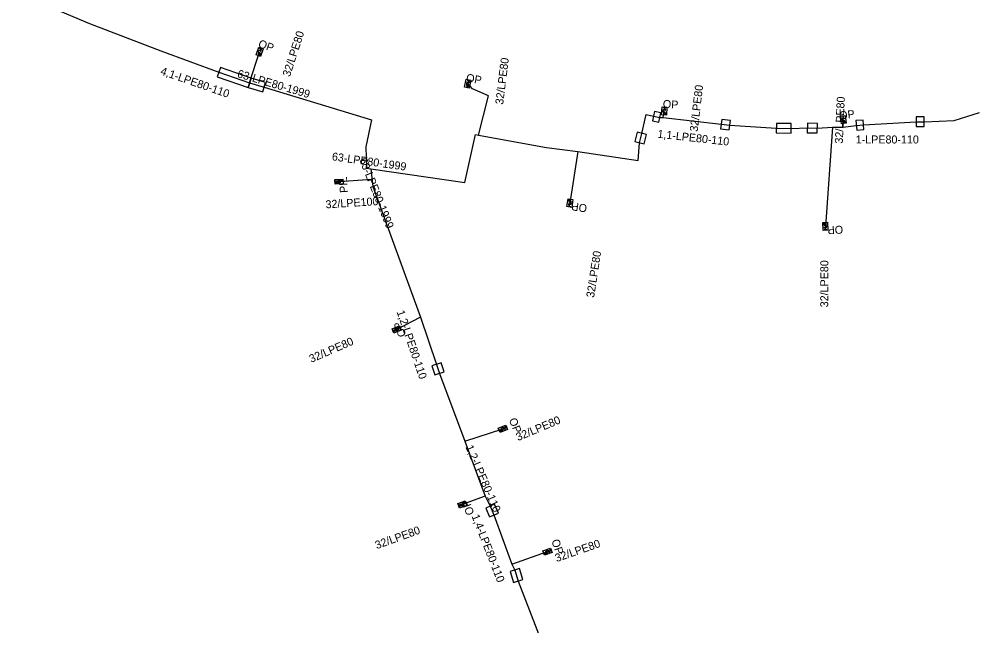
# Model space of a CAD drawing. Extents: x -762509 to -761250, y -1153000 to -1152256.
# Drawn here: x -761556.9 to -761437.4, y -1152409.7 to -1152334 of the extents above; entities that cross this region are included whole.
import ezdxf

# ---------------------------------------------------------------- set-up
doc = ezdxf.new("R2010")
doc.units = 0
for name, color, linetype in [('Vrstva 21', 7, 'Continuous'), ('Vrstva 29', 7, 'Continuous'), ('Vrstva 31', 7, 'Continuous'), ('Vrstva 32', 7, 'Continuous')]:
    doc.layers.add(name, color=color, linetype=linetype)

msp = doc.modelspace()

# ---------------------------------------------------------------- linework, layer by layer
at = {"layer": 'Vrstva 21'}
for points in [[(-761582.89, -1152319.81), (-761579.97, -1152321.01), (-761566.93, -1152326.59), (-761564.15, -1152327.67), (-761562.41, -1152328.48), (-761561.34, -1152328.94), (-761548.12, -1152334.52), (-761539.24, -1152337.93), (-761531.97, -1152340.58), (-761528.13, -1152341.92), (-761526.3, -1152342.45), (-761512.91, -1152346.54), (-761513.62, -1152349.91), (-761513.51, -1152352.59), (-761512.99, -1152352.67)], [(-761512.99, -1152352.67), (-761501.24, -1152354.37), (-761499.92, -1152348.35), (-761499.54, -1152348.44), (-761491.06, -1152349.98), (-761487.11, -1152350.48), (-761479.58, -1152351.6), (-761479.41, -1152349.39), (-761479.14, -1152348.23), (-761478.58, -1152345.89), (-761477.67, -1152346.08), (-761476.89, -1152346.26), (-761476.46, -1152346.24), (-761469.21, -1152347.08), (-761468.14, -1152347.2), (-761462.33, -1152347.58), (-761460.48, -1152347.61), (-761458.44, -1152347.54), (-761457.21, -1152347.58), (-761455.3, -1152347.46), (-761454.02, -1152347.46), (-761452.33, -1152347.23), (-761451.42, -1152347.16), (-761444.84, -1152346.77), (-761443.87, -1152346.77), (-761440.11, -1152346.61), (-761436.95, -1152345.64)], [(-761512.99, -1152352.67), (-761512.75, -1152354.87), (-761506.77, -1152371.17), (-761504.79, -1152377.08), (-761504.41, -1152378.2), (-761501.26, -1152386.66), (-761500.37, -1152389.03), (-761498.7, -1152393.56), (-761498.08, -1152394.78), (-761497.6, -1152395.89), (-761495.38, -1152402.02), (-761495, -1152402.77), (-761494.58, -1152404.14), (-761490.85, -1152413.85)]]:
    msp.add_lwpolyline(points, dxfattribs=at)
at = {"layer": 'Vrstva 29'}
for points in [[(-761532.17, -1152341.15), (-761528.33, -1152342.49), (-761527.93, -1152341.35), (-761531.77, -1152340.01)], [(-761528.3, -1152342.5), (-761526.47, -1152343.03), (-761526.13, -1152341.87), (-761527.96, -1152341.34)], [(-761477.8, -1152346.66), (-761477.02, -1152346.84), (-761476.76, -1152345.68), (-761477.54, -1152345.5)], [(-761469.28, -1152347.68), (-761468.21, -1152347.8), (-761468.07, -1152346.6), (-761469.14, -1152346.48)], [(-761452.28, -1152347.83), (-761451.37, -1152347.76), (-761451.47, -1152346.56), (-761452.38, -1152346.63)], [(-761444.84, -1152347.37), (-761443.87, -1152347.37), (-761443.87, -1152346.17), (-761444.84, -1152346.17)], [(-761462.34, -1152348.18), (-761460.49, -1152348.21), (-761460.47, -1152347.01), (-761462.32, -1152346.98)], [(-761458.46, -1152348.14), (-761457.23, -1152348.18), (-761457.19, -1152346.98), (-761458.42, -1152346.94)], [(-761479.72, -1152348.09), (-761479.99, -1152349.25), (-761478.83, -1152349.53), (-761478.56, -1152348.37)], [(-761505.36, -1152377.27), (-761504.98, -1152378.39), (-761503.84, -1152378.01), (-761504.22, -1152376.89)], [(-761498.63, -1152395.02), (-761498.15, -1152396.13), (-761497.05, -1152395.65), (-761497.53, -1152394.54)], [(-761495.57, -1152402.95), (-761495.15, -1152404.32), (-761494.01, -1152403.96), (-761494.43, -1152402.59)]]:
    msp.add_lwpolyline(points, close=True, dxfattribs=at)
at = {"layer": 'Vrstva 31'}
for points in [[(-761528.13, -1152341.92), (-761526.88, -1152338.05)], [(-761499.54, -1152348.44), (-761498.28, -1152343.52), (-761500.3, -1152342.68), (-761500.88, -1152342.01)], [(-761476.46, -1152346.24), (-761476.33, -1152345.45)], [(-761454.02, -1152347.46), (-761453.96, -1152346.51)], [(-761455.3, -1152347.46), (-761456.2, -1152359.84)], [(-761487.11, -1152350.48), (-761488.11, -1152356.93)], [(-761512.82, -1152354), (-761516.98, -1152354.26)], [(-761506.77, -1152371.17), (-761509.76, -1152372.72)], [(-761501.26, -1152386.66), (-761496.49, -1152385.13)], [(-761498.7, -1152393.56), (-761501.56, -1152394.59)], [(-761495.38, -1152402.02), (-761490.91, -1152400.47)]]:
    msp.add_lwpolyline(points, dxfattribs=at)
at = {"layer": 'Vrstva 32'}
for p, q in [((-761527.112, -1152338.179), (-761526.783, -1152338.297)), ((-761526.978, -1152337.803), (-761526.649, -1152337.921)), ((-761526.581, -1152337.732), (-761526.911, -1152337.614)), ((-761526.736, -1152337.676), (-761526.804, -1152337.865)), ((-761501.012, -1152341.78), (-761500.669, -1152341.85)), ((-761500.629, -1152341.653), (-761500.972, -1152341.583)), ((-761500.79, -1152341.62), (-761500.831, -1152341.817)), ((-761501.091, -1152342.171), (-761500.748, -1152342.241)), ((-761476.518, -1152345.638), (-761476.169, -1152345.662)), ((-761476.491, -1152345.24), (-761476.142, -1152345.264)), ((-761476.128, -1152345.063), (-761476.477, -1152345.039)), ((-761476.292, -1152345.052), (-761476.306, -1152345.252)), ((-761453.836, -1152346.091), (-761454.183, -1152346.134)), ((-761454.158, -1152346.334), (-761453.811, -1152346.291)), ((-761454.109, -1152346.73), (-761453.762, -1152346.687)), ((-761453.999, -1152346.111), (-761453.975, -1152346.311)), ((-761517.39, -1152354.111), (-761517.368, -1152354.46)), ((-761517.38, -1152354.275), (-761517.179, -1152354.263)), ((-761517.168, -1152354.447), (-761517.19, -1152354.098)), ((-761516.77, -1152354.423), (-761516.791, -1152354.073)), ((-761488.345, -1152357.298), (-761487.999, -1152357.352)), ((-761487.968, -1152357.153), (-761488.314, -1152357.099)), ((-761487.907, -1152356.759), (-761488.253, -1152356.705)), ((-761488.182, -1152357.323), (-761488.151, -1152357.125)), ((-761456.035, -1152359.631), (-761456.385, -1152359.648)), ((-761456.015, -1152360.03), (-761456.365, -1152360.047)), ((-761456.355, -1152360.248), (-761456.005, -1152360.23)), ((-761456.19, -1152360.24), (-761456.2, -1152360.039)), ((-761510.196, -1152372.703), (-761510.068, -1152373.029)), ((-761510.136, -1152372.857), (-761509.949, -1152372.783)), ((-761509.881, -1152372.955), (-761510.009, -1152372.63)), ((-761509.51, -1152372.81), (-761509.638, -1152372.484)), ((-761496.741, -1152385.044), (-761496.608, -1152385.368)), ((-761496.372, -1152384.893), (-761496.239, -1152385.216)), ((-761496.116, -1152384.987), (-761496.302, -1152385.064)), ((-761496.053, -1152385.14), (-761496.186, -1152384.816)), ((-761501.996, -1152394.56), (-761501.877, -1152394.89)), ((-761501.94, -1152394.716), (-761501.751, -1152394.648)), ((-761501.688, -1152394.822), (-761501.807, -1152394.492)), ((-761501.313, -1152394.686), (-761501.431, -1152394.357)), ((-761491.157, -1152400.373), (-761491.039, -1152400.702)), ((-761490.782, -1152400.238), (-761490.664, -1152400.568)), ((-761490.53, -1152400.345), (-761490.719, -1152400.413)), ((-761490.474, -1152400.5), (-761490.592, -1152400.171))]:
    msp.add_line(p, q, dxfattribs=at)
for points in [[(-761526.43, -1152337.679), (-761526.766, -1152338.621), (-761527.331, -1152338.42), (-761526.995, -1152337.478), (-761526.43, -1152337.679)], [(-761526.682, -1152338.014), (-761526.918, -1152337.93), (-761526.969, -1152337.927), (-761527.011, -1152337.945), (-761527.041, -1152337.978), (-761527.05, -1152338.006), (-761527.049, -1152338.051), (-761527.027, -1152338.089), (-761526.986, -1152338.119), (-761526.749, -1152338.203)], [(-761526.783, -1152338.297), (-761526.826, -1152338.419), (-761526.856, -1152338.453), (-761526.877, -1152338.462), (-761526.912, -1152338.464), (-761526.959, -1152338.447), (-761526.986, -1152338.423), (-761526.996, -1152338.403), (-761526.998, -1152338.358), (-761526.954, -1152338.236)], [(-761500.486, -1152341.58), (-761500.686, -1152342.56), (-761501.274, -1152342.44), (-761501.074, -1152341.46), (-761500.486, -1152341.58)], [(-761500.689, -1152341.947), (-761500.935, -1152341.897), (-761500.985, -1152341.901), (-761501.024, -1152341.924), (-761501.049, -1152341.962), (-761501.055, -1152341.991), (-761501.046, -1152342.035), (-761501.02, -1152342.07), (-761500.975, -1152342.094), (-761500.729, -1152342.144)], [(-761500.748, -1152342.241), (-761500.774, -1152342.368), (-761500.799, -1152342.406), (-761500.818, -1152342.417), (-761500.853, -1152342.424), (-761500.902, -1152342.415), (-761500.932, -1152342.394), (-761500.944, -1152342.376), (-761500.953, -1152342.332), (-761500.927, -1152342.204)], [(-761475.996, -1152344.972), (-761476.065, -1152345.97), (-761476.663, -1152345.928), (-761476.595, -1152344.931), (-761475.996, -1152344.972)], [(-761476.148, -1152345.362), (-761476.399, -1152345.345), (-761476.449, -1152345.356), (-761476.484, -1152345.385), (-761476.504, -1152345.425), (-761476.506, -1152345.454), (-761476.491, -1152345.497), (-761476.461, -1152345.528), (-761476.413, -1152345.546), (-761476.162, -1152345.563)], [(-761476.169, -1152345.662), (-761476.178, -1152345.791), (-761476.198, -1152345.832), (-761476.215, -1152345.846), (-761476.249, -1152345.858), (-761476.299, -1152345.854), (-761476.33, -1152345.838), (-761476.345, -1152345.822), (-761476.359, -1152345.779), (-761476.351, -1152345.649)], [(-761453.724, -1152345.977), (-761453.601, -1152346.969), (-761454.196, -1152347.043), (-761454.319, -1152346.05), (-761453.724, -1152345.977)], [(-761453.799, -1152346.389), (-761454.048, -1152346.42), (-761454.095, -1152346.44), (-761454.124, -1152346.475), (-761454.135, -1152346.518), (-761454.132, -1152346.547), (-761454.11, -1152346.587), (-761454.073, -1152346.611), (-761454.023, -1152346.619), (-761453.774, -1152346.588)], [(-761453.762, -1152346.687), (-761453.746, -1152346.816), (-761453.758, -1152346.859), (-761453.772, -1152346.876), (-761453.803, -1152346.894), (-761453.852, -1152346.9), (-761453.887, -1152346.891), (-761453.904, -1152346.878), (-761453.926, -1152346.838), (-761453.942, -1152346.709)], [(-761517.498, -1152353.992), (-761516.5, -1152353.93), (-761516.462, -1152354.529), (-761517.46, -1152354.591), (-761517.498, -1152353.992)], [(-761517.091, -1152354.092), (-761517.075, -1152354.342), (-761517.058, -1152354.39), (-761517.025, -1152354.421), (-761516.982, -1152354.436), (-761516.953, -1152354.434), (-761516.912, -1152354.414), (-761516.885, -1152354.38), (-761516.875, -1152354.33), (-761516.89, -1152354.079)], [(-761516.791, -1152354.073), (-761516.662, -1152354.065), (-761516.619, -1152354.079), (-761516.603, -1152354.094), (-761516.587, -1152354.127), (-761516.584, -1152354.176), (-761516.595, -1152354.21), (-761516.609, -1152354.227), (-761516.65, -1152354.247), (-761516.78, -1152354.255)], [(-761488.483, -1152357.378), (-761488.33, -1152356.39), (-761487.737, -1152356.481), (-761487.891, -1152357.47), (-761488.483, -1152357.378)], [(-761488.299, -1152357.002), (-761488.051, -1152357.04), (-761488, -1152357.034), (-761487.963, -1152357.008), (-761487.939, -1152356.969), (-761487.935, -1152356.941), (-761487.945, -1152356.896), (-761487.974, -1152356.863), (-761488.02, -1152356.841), (-761488.268, -1152356.803)], [(-761488.253, -1152356.705), (-761488.233, -1152356.577), (-761488.21, -1152356.538), (-761488.191, -1152356.525), (-761488.157, -1152356.517), (-761488.107, -1152356.524), (-761488.077, -1152356.543), (-761488.063, -1152356.56), (-761488.053, -1152356.605), (-761488.073, -1152356.733)], [(-761456.475, -1152360.354), (-761456.524, -1152359.355), (-761455.925, -1152359.325), (-761455.875, -1152360.324), (-761456.475, -1152360.354)], [(-761456.385, -1152359.648), (-761456.391, -1152359.519), (-761456.376, -1152359.476), (-761456.361, -1152359.46), (-761456.329, -1152359.444), (-761456.279, -1152359.442), (-761456.245, -1152359.454), (-761456.228, -1152359.468), (-761456.209, -1152359.51), (-761456.203, -1152359.639)], [(-761456.37, -1152359.948), (-761456.119, -1152359.936), (-761456.071, -1152359.919), (-761456.039, -1152359.887), (-761456.024, -1152359.844), (-761456.026, -1152359.815), (-761456.045, -1152359.774), (-761456.079, -1152359.746), (-761456.129, -1152359.735), (-761456.38, -1152359.747)], [(-761510.335, -1152372.623), (-761509.404, -1152372.258), (-761509.185, -1152372.816), (-761510.116, -1152373.182), (-761510.335, -1152372.623)], [(-761509.917, -1152372.593), (-761509.825, -1152372.827), (-761509.794, -1152372.868), (-761509.753, -1152372.887), (-761509.708, -1152372.887), (-761509.681, -1152372.877), (-761509.648, -1152372.846), (-761509.633, -1152372.804), (-761509.638, -1152372.754), (-761509.73, -1152372.52)], [(-761509.638, -1152372.484), (-761509.517, -1152372.436), (-761509.471, -1152372.437), (-761509.451, -1152372.446), (-761509.426, -1152372.472), (-761509.408, -1152372.518), (-761509.409, -1152372.554), (-761509.417, -1152372.575), (-761509.45, -1152372.606), (-761509.571, -1152372.653)], [(-761495.913, -1152385.217), (-761496.838, -1152385.598), (-761497.066, -1152385.043), (-761496.141, -1152384.663), (-761495.913, -1152385.217)], [(-761496.331, -1152385.254), (-761496.426, -1152385.022), (-761496.458, -1152384.982), (-761496.499, -1152384.963), (-761496.544, -1152384.963), (-761496.571, -1152384.974), (-761496.603, -1152385.006), (-761496.618, -1152385.048), (-761496.612, -1152385.098), (-761496.516, -1152385.33)], [(-761496.608, -1152385.368), (-761496.728, -1152385.418), (-761496.774, -1152385.418), (-761496.794, -1152385.409), (-761496.819, -1152385.384), (-761496.838, -1152385.337), (-761496.838, -1152385.301), (-761496.83, -1152385.281), (-761496.797, -1152385.249), (-761496.677, -1152385.2)], [(-761502.132, -1152394.477), (-761501.191, -1152394.138), (-761500.988, -1152394.702), (-761501.929, -1152395.041), (-761502.132, -1152394.477)], [(-761501.714, -1152394.459), (-761501.629, -1152394.695), (-761501.599, -1152394.736), (-761501.558, -1152394.757), (-761501.513, -1152394.759), (-761501.486, -1152394.749), (-761501.452, -1152394.719), (-761501.436, -1152394.678), (-761501.439, -1152394.627), (-761501.525, -1152394.391)], [(-761501.431, -1152394.357), (-761501.309, -1152394.313), (-761501.264, -1152394.315), (-761501.244, -1152394.325), (-761501.22, -1152394.351), (-761501.203, -1152394.398), (-761501.205, -1152394.434), (-761501.214, -1152394.454), (-761501.247, -1152394.484), (-761501.37, -1152394.528)], [(-761490.338, -1152400.584), (-761491.28, -1152400.921), (-761491.482, -1152400.356), (-761490.54, -1152400.019), (-761490.338, -1152400.584)], [(-761491.039, -1152400.702), (-761491.162, -1152400.746), (-761491.207, -1152400.744), (-761491.227, -1152400.734), (-761491.251, -1152400.708), (-761491.268, -1152400.661), (-761491.266, -1152400.625), (-761491.257, -1152400.605), (-761491.223, -1152400.575), (-761491.101, -1152400.531)], [(-761490.757, -1152400.601), (-761490.841, -1152400.365), (-761490.871, -1152400.324), (-761490.911, -1152400.303), (-761490.957, -1152400.301), (-761490.984, -1152400.311), (-761491.018, -1152400.341), (-761491.034, -1152400.382), (-761491.031, -1152400.433), (-761490.946, -1152400.669)]]:
    msp.add_lwpolyline(points, dxfattribs=at)

# ---------------------------------------------------------------- texts
at = {"layer": 'Vrstva 21'}
for rotation, p in [(343.53634, (-761529.75, -1152341.19)), (351.99754, (-761517.9, -1152351.58)), (291.72331, (-761514.46, -1152351.52))]:
    msp.add_text('63-LPE80-1999', height=1, rotation=rotation, dxfattribs=at).set_placement(p)
at = {"layer": 'Vrstva 29'}
for s, rotation, p in [('4,1-LPE80-110', 340.76314, (-761539.36, -1152340.84)), ('1,1-LPE80-110', 353.60104, (-761477.21, -1152348.76)), ('1,2-LPE80-110', 288.74134, (-761509.78, -1152370.5)), ('1,2-LPE80-110', 293.38522, (-761501.19, -1152387.4)), ('1,4-LPE80-110', 291.31108, (-761500.42, -1152396.03))]:
    msp.add_text(s, height=1, rotation=rotation, dxfattribs=at).set_placement(p)
msp.add_text('1-LPE80-110', height=1, dxfattribs=at).set_placement((-761452.4, -1152349.49))
at = {"layer": 'Vrstva 31'}
for s, rotation, p in [('32/LPE80', 72.09968, (-761523.1, -1152341.22)), ('32/LPE80', 72.09968, (-761523.1, -1152341.22)), ('32/LPE80', 82.92393, (-761496.46, -1152344.67)), ('32/LPE80', 82.92393, (-761496.46, -1152344.67)), ('32/LPE80', 83.20027, (-761472.16, -1152348.06)), ('32/LPE80', 83.20027, (-761472.16, -1152348.06)), ('32/LPE80', 87.47277, (-761454.02, -1152349.52)), ('32/LPE80', 87.47277, (-761454.02, -1152349.52)), ('32/LPE100', 3.57633, (-761518.62, -1152357.6)), ('32/LPE100', 3.57633, (-761518.62, -1152357.6)), ('32/LPE80', 81.1871, (-761485.1, -1152368.79)), ('32/LPE80', 81.1871, (-761485.1, -1152368.79)), ('32/LPE80', 89.87632, (-761455.84, -1152369.95)), ('32/LPE80', 89.87632, (-761455.84, -1152369.95)), ('32/LPE80', 23.43259, (-761520.44, -1152376.9)), ('32/LPE80', 23.43259, (-761520.44, -1152376.9)), ('32/LPE80', 22.7839, (-761494.6, -1152386.67)), ('32/LPE80', 22.7839, (-761494.6, -1152386.67)), ('32/LPE80', 19.80597, (-761512.25, -1152400.17)), ('32/LPE80', 19.80597, (-761512.25, -1152400.17)), ('32/LPE80', 19.1243, (-761489.77, -1152401.78)), ('32/LPE80', 19.1243, (-761489.77, -1152401.78))]:
    msp.add_text(s, height=1, rotation=rotation, dxfattribs=at).set_placement(p)
at = {"layer": 'Vrstva 32'}
for s, rotation, p in [('OP', 340.35987, (-761527.14, -1152337.42)), ('OP', 340.35987, (-761527.14, -1152337.42)), ('OP', 348.49389, (-761501.15, -1152341.72)), ('OP', 348.49389, (-761501.15, -1152341.72)), ('OP', 356.06608, (-761476.53, -1152345.03)), ('OP', 356.06608, (-761476.53, -1152345.03)), ('OP', 7.07008, (-761454.4, -1152346.51)), ('OP', 7.07008, (-761454.4, -1152346.51)), ('PIL', 93.57633, (-761515.85, -1152355.63)), ('PIL', 93.57633, (-761515.85, -1152355.63)), ('OP', 171.1871, (-761485.91, -1152357.13)), ('OP', 171.1871, (-761485.91, -1152357.13)), ('OP', 182.84639, (-761454.01, -1152359.74)), ('OP', 182.84639, (-761454.01, -1152359.74)), ('OP', 111.43001, (-761508.53, -1152373.43)), ('OP', 111.43001, (-761508.53, -1152373.43)), ('OP', 292.3594, (-761495.77, -1152384)), ('OP', 292.3594, (-761495.77, -1152384)), ('OP', 109.80597, (-761500.05, -1152395.71)), ('OP', 109.80597, (-761500.05, -1152395.71)), ('OP', 289.67939, (-761490.45, -1152399.12)), ('OP', 289.67939, (-761490.45, -1152399.12))]:
    msp.add_text(s, height=1, rotation=rotation, dxfattribs=at).set_placement(p)

doc.saveas('drawing.dxf')
